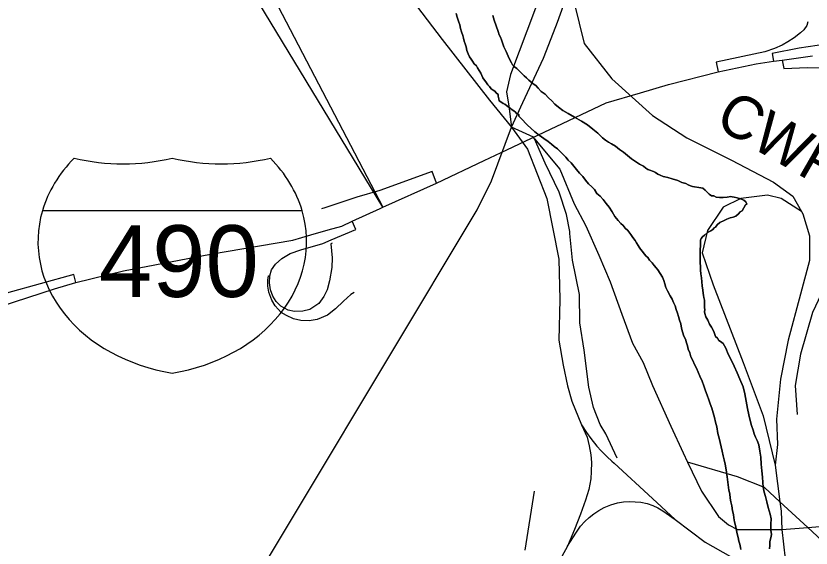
# Model space of a CAD drawing. Extents: x 0 to 96.2, y -27.5 to 31.3.
# Drawn here: x 46.371 to 47.422, y 16.88 to 17.583 of the extents above; entities that cross this region are included whole.
import ezdxf

# ---------------------------------------------------------------- set-up
doc = ezdxf.new("R2010")
doc.units = 0
for name, color, linetype in [('TB1', 7, 'Continuous'), ('TB_INDEX', 7, 'Continuous'), ('TB_PP_50x10_GRID', 7, 'Continuous'), ('TB_PROF_20x5', 7, 'Continuous'), ('TB_PROF_20x5_GRID', 7, 'Continuous'), ('TB_PSNSUM', 7, 'Continuous'), ('TB_SIGN_XS_GRID', 7, 'Continuous'), ('TB_SUPER_50x1', 7, 'Continuous')]:
    doc.layers.add(name, color=color, linetype=linetype)

msp = doc.modelspace()

# ---------------------------------------------------------------- linework, layer by layer
at = {"layer": 'TB1'}
msp.add_lwpolyline([(46.8522, 17.3284), (46.8555, 17.3299), (46.9267, 17.3616), (46.9897, 17.3916), (47.0195, 17.4057), (47.1509, 17.4678), (47.196, 17.481), (47.2332, 17.4919), (47.2987, 17.5086), (47.3491, 17.5196), (47.3717, 17.5227), (47.3835, 17.5244), (47.4236, 17.5299)], dxfattribs=at)
at = {"layer": 'TB_INDEX'}
for points in [[(46.9524, 17.5858), (46.954, 17.5809), (46.9552, 17.5771), (46.956, 17.5745), (46.9572, 17.5707), (46.9584, 17.5661), (46.9596, 17.5616), (46.9612, 17.5567), (46.9623, 17.5532), (46.9631, 17.5495)], [(46.9631, 17.5495), (46.9623, 17.5532), (46.9612, 17.5567), (46.9596, 17.5616), (46.9584, 17.5661), (46.9572, 17.5707), (46.956, 17.5745), (46.9552, 17.5771), (46.954, 17.5809), (46.9524, 17.5858)], [(47.2058, 17.3799), (47.2031, 17.3817), (47.2001, 17.3843), (47.1947, 17.3869), (47.1897, 17.3903), (47.1844, 17.394), (47.179, 17.3982), (47.1736, 17.4026), (47.1682, 17.4064), (47.1629, 17.4105), (47.1579, 17.4135), (47.1537, 17.4161), (47.1498, 17.4187), (47.146, 17.4217), (47.1395, 17.4277), (47.1333, 17.4329), (47.126, 17.4386), (47.118, 17.4438), (47.1088, 17.449), (47.1004, 17.4538), (47.0935, 17.4579), (47.0877, 17.462), (47.0828, 17.4662), (47.0789, 17.4703), (47.0747, 17.4744), (47.07, 17.4793), (47.0647, 17.483), (47.0608, 17.4872), (47.0577, 17.4906), (47.0543, 17.4928), (47.0512, 17.4954), (47.0485, 17.498), (47.0454, 17.5007), (47.0424, 17.5037), (47.0393, 17.5067), (47.0358, 17.5101), (47.0327, 17.5131), (47.0297, 17.5153), (47.027, 17.5179), (47.0258, 17.5206), (47.0235, 17.5247), (47.0211, 17.5296), (47.0184, 17.5357), (47.0157, 17.5417), (47.0137, 17.547), (47.0125, 17.5512), (47.0109, 17.5546), (47.0094, 17.5576), (47.0082, 17.5622), (47.0026, 17.5769), (47.001, 17.5834)], [(47.001, 17.5834), (47.0026, 17.5769), (47.0082, 17.5622), (47.0094, 17.5576), (47.0109, 17.5546), (47.0125, 17.5512), (47.0137, 17.547), (47.0157, 17.5417), (47.0184, 17.5357), (47.0211, 17.5296), (47.0235, 17.5247), (47.0258, 17.5206), (47.027, 17.5179), (47.0297, 17.5153), (47.0327, 17.5131), (47.0358, 17.5101), (47.0393, 17.5067), (47.0424, 17.5037), (47.0454, 17.5007), (47.0485, 17.498), (47.0512, 17.4954), (47.0543, 17.4928), (47.0577, 17.4906), (47.0608, 17.4872), (47.0647, 17.483), (47.07, 17.4793), (47.0747, 17.4744), (47.0789, 17.4703), (47.0828, 17.4662), (47.0877, 17.462), (47.0935, 17.4579), (47.1004, 17.4538), (47.1088, 17.449), (47.118, 17.4438), (47.126, 17.4386), (47.1333, 17.4329), (47.1395, 17.4277), (47.146, 17.4217), (47.1498, 17.4187), (47.1537, 17.4161), (47.1579, 17.4135), (47.1629, 17.4105), (47.1682, 17.4064), (47.1736, 17.4026), (47.179, 17.3982), (47.1844, 17.394), (47.1897, 17.3903), (47.1947, 17.3869), (47.2001, 17.3843), (47.2031, 17.3817), (47.2058, 17.3799)], [(46.9631, 17.5495), (46.9643, 17.5457), (46.9655, 17.5419), (46.9664, 17.537), (46.9683, 17.5328), (46.9703, 17.5286), (46.9722, 17.5256), (46.9741, 17.523), (46.9765, 17.5192), (46.9792, 17.5166), (46.9807, 17.5139), (46.983, 17.5106), (46.985, 17.5072), (46.9862, 17.5041), (46.9877, 17.5011), (46.9901, 17.4977), (46.9916, 17.4955), (46.9943, 17.4917), (46.9966, 17.4894), (46.9989, 17.4864), (47.0016, 17.4846), (47.0035, 17.4831), (47.0055, 17.4812), (47.0078, 17.4789), (47.0078, 17.4767), (47.009, 17.4732), (47.0094, 17.4706), (47.0129, 17.4684), (47.0148, 17.4672), (47.0167, 17.4661), (47.019, 17.4642), (47.0224, 17.4616), (47.0244, 17.4605), (47.0263, 17.4586), (47.0286, 17.4571), (47.0309, 17.4556), (47.0324, 17.4538), (47.0351, 17.4523), (47.0355, 17.4504), (47.0378, 17.4474), (47.0467, 17.4384), (47.0513, 17.4342), (47.0563, 17.4297), (47.062, 17.4252), (47.0682, 17.4208), (47.0739, 17.4166), (47.0785, 17.4133), (47.082, 17.4103), (47.0862, 17.4069), (47.0905, 17.4032), (47.0939, 17.3998), (47.0974, 17.396), (47.1005, 17.3923), (47.1043, 17.3885), (47.1078, 17.3844), (47.1113, 17.3799), (47.1155, 17.375), (47.1198, 17.3705), (47.1236, 17.3656), (47.1275, 17.3607), (47.1317, 17.3569), (47.1352, 17.3532), (47.1383, 17.3479), (47.1429, 17.3445), (47.1468, 17.34), (47.1506, 17.3347), (47.1549, 17.3298), (47.1587, 17.3238), (47.1622, 17.3178), (47.1665, 17.3125), (47.17, 17.3084), (47.173, 17.3057), (47.1757, 17.3023), (47.1792, 17.299), (47.1831, 17.2941), (47.1858, 17.2899), (47.1889, 17.2858), (47.1908, 17.2828), (47.1928, 17.2794), (47.1943, 17.2771), (47.1962, 17.2745), (47.1986, 17.2715), (47.2009, 17.2685), (47.2036, 17.2654), (47.2059, 17.2636), (47.2082, 17.2598), (47.2113, 17.2564), (47.214, 17.253), (47.2167, 17.25), (47.219, 17.247), (47.2252, 17.2376), (47.2268, 17.233), (47.2284, 17.2285), (47.2296, 17.224), (47.2316, 17.2194), (47.2354, 17.213), (47.2378, 17.2085), (47.2397, 17.2039), (47.2417, 17.1998), (47.2433, 17.1949), (47.2449, 17.1899)], [(47.2449, 17.1899), (47.2433, 17.1949), (47.2417, 17.1998), (47.2397, 17.2039), (47.2378, 17.2085), (47.2354, 17.213), (47.2316, 17.2194), (47.2296, 17.224), (47.2284, 17.2285), (47.2268, 17.233), (47.2252, 17.2376), (47.219, 17.247), (47.2167, 17.25), (47.214, 17.253), (47.2113, 17.2564), (47.2082, 17.2598), (47.2059, 17.2636), (47.2036, 17.2654), (47.2009, 17.2685), (47.1986, 17.2715), (47.1962, 17.2745), (47.1943, 17.2771), (47.1928, 17.2794), (47.1908, 17.2828), (47.1889, 17.2858), (47.1858, 17.2899), (47.1831, 17.2941), (47.1792, 17.299), (47.1757, 17.3023), (47.173, 17.3057), (47.17, 17.3084), (47.1665, 17.3125), (47.1622, 17.3178), (47.1587, 17.3238), (47.1549, 17.3298), (47.1506, 17.3347), (47.1468, 17.34), (47.1429, 17.3445), (47.1383, 17.3479), (47.1352, 17.3532), (47.1317, 17.3569), (47.1275, 17.3607), (47.1236, 17.3656), (47.1198, 17.3705), (47.1155, 17.375), (47.1113, 17.3799), (47.1078, 17.3844), (47.1043, 17.3885), (47.1005, 17.3923), (47.0974, 17.396), (47.0939, 17.3998), (47.0905, 17.4032), (47.0862, 17.4069), (47.082, 17.4103), (47.0785, 17.4133), (47.0739, 17.4166), (47.0682, 17.4208), (47.062, 17.4252), (47.0563, 17.4297), (47.0513, 17.4342), (47.0467, 17.4384), (47.0378, 17.4474), (47.0355, 17.4504), (47.0351, 17.4523), (47.0324, 17.4538), (47.0309, 17.4556), (47.0286, 17.4571), (47.0263, 17.4586), (47.0244, 17.4605), (47.0224, 17.4616), (47.019, 17.4642), (47.0167, 17.4661), (47.0148, 17.4672), (47.0129, 17.4684), (47.0094, 17.4706), (47.009, 17.4732), (47.0078, 17.4767), (47.0078, 17.4789), (47.0055, 17.4812), (47.0035, 17.4831), (47.0016, 17.4846), (46.9989, 17.4864), (46.9966, 17.4894), (46.9943, 17.4917), (46.9916, 17.4955), (46.9901, 17.4977), (46.9877, 17.5011), (46.9862, 17.5041), (46.985, 17.5072), (46.983, 17.5106), (46.9807, 17.5139), (46.9792, 17.5166), (46.9765, 17.5192), (46.9741, 17.523), (46.9722, 17.5256), (46.9703, 17.5286), (46.9683, 17.5328), (46.9664, 17.537), (46.9655, 17.5419), (46.9643, 17.5457), (46.9631, 17.5495)], [(47.3357, 17.0736), (47.334, 17.0835), (47.3316, 17.0926), (47.3273, 17.1028), (47.3238, 17.1111), (47.3199, 17.1198), (47.316, 17.1285), (47.3121, 17.136), (47.3089, 17.1436), (47.3054, 17.15), (47.3016, 17.1526), (47.2997, 17.1537), (47.2977, 17.1568), (47.2954, 17.159), (47.2942, 17.1617), (47.2934, 17.1643), (47.2923, 17.1677), (47.2899, 17.1715), (47.2872, 17.1756), (47.2849, 17.1805), (47.2825, 17.1851), (47.2813, 17.1896), (47.2805, 17.1919), (47.2809, 17.1946), (47.2808, 17.1968), (47.2808, 17.2003), (47.2808, 17.2037), (47.2807, 17.2071), (47.2799, 17.2105), (47.2795, 17.2132), (47.2791, 17.2162), (47.2786, 17.2204), (47.2778, 17.2261), (47.277, 17.2314), (47.2765, 17.2367), (47.2757, 17.242), (47.2752, 17.2469), (47.2752, 17.2515), (47.2751, 17.2564), (47.275, 17.2614), (47.2749, 17.2671), (47.2749, 17.2731), (47.2752, 17.2796), (47.2754, 17.2865), (47.2762, 17.2887), (47.278, 17.291), (47.2807, 17.293), (47.2848, 17.2964), (47.2889, 17.2988), (47.2916, 17.3007), (47.2934, 17.3026), (47.2953, 17.3038), (47.2972, 17.3065), (47.3009, 17.3096), (47.3028, 17.3107), (47.3051, 17.3115), (47.3074, 17.3127), (47.3104, 17.3142), (47.3145, 17.3158), (47.3187, 17.317), (47.3221, 17.3182), (47.3255, 17.3213), (47.3277, 17.3239), (47.3303, 17.3251), (47.3326, 17.3293), (47.3348, 17.3331), (47.3367, 17.3339), (47.3355, 17.337), (47.3328, 17.3392), (47.3282, 17.3411), (47.3237, 17.3425), (47.3198, 17.3432), (47.3172, 17.3436), (47.3153, 17.3439), (47.3107, 17.3431), (47.3054, 17.3427), (47.3005, 17.343), (47.2963, 17.3433), (47.2932, 17.3448), (47.2898, 17.3451), (47.2868, 17.3474), (47.2841, 17.35), (47.2814, 17.3526), (47.2783, 17.3549), (47.276, 17.3556), (47.265, 17.3574), (47.2623, 17.3581), (47.2592, 17.3596), (47.2558, 17.3611), (47.2509, 17.3625), (47.2455, 17.3651), (47.2379, 17.3673), (47.2322, 17.3692), (47.2284, 17.3699), (47.2261, 17.3706), (47.2222, 17.3725), (47.2192, 17.3736), (47.2157, 17.3758), (47.2131, 17.3773), (47.2085, 17.3791), (47.2058, 17.3799)], [(47.2058, 17.3799), (47.2085, 17.3791), (47.2131, 17.3773), (47.2157, 17.3758), (47.2192, 17.3736), (47.2222, 17.3725), (47.2261, 17.3706), (47.2284, 17.3699), (47.2322, 17.3692), (47.2379, 17.3673), (47.2455, 17.3651), (47.2509, 17.3625), (47.2558, 17.3611), (47.2592, 17.3596), (47.2623, 17.3581), (47.265, 17.3574), (47.276, 17.3556), (47.2783, 17.3549), (47.2814, 17.3526), (47.2841, 17.35), (47.2868, 17.3474), (47.2898, 17.3451), (47.2932, 17.3448), (47.2963, 17.3433), (47.3005, 17.343), (47.3054, 17.3427), (47.3107, 17.3431), (47.3153, 17.3439), (47.3172, 17.3436), (47.3198, 17.3432), (47.3237, 17.3425), (47.3282, 17.3411), (47.3328, 17.3392), (47.3355, 17.337), (47.3367, 17.3339), (47.3348, 17.3331), (47.3326, 17.3293), (47.3303, 17.3251), (47.3277, 17.3239), (47.3255, 17.3213), (47.3221, 17.3182), (47.3187, 17.317), (47.3145, 17.3158), (47.3104, 17.3142), (47.3074, 17.3127), (47.3051, 17.3115), (47.3028, 17.3107), (47.3009, 17.3096), (47.2972, 17.3065), (47.2953, 17.3038), (47.2934, 17.3026), (47.2916, 17.3007), (47.2889, 17.2988), (47.2848, 17.2964), (47.2807, 17.293), (47.278, 17.291), (47.2762, 17.2887), (47.2754, 17.2865), (47.2752, 17.2796), (47.2749, 17.2731), (47.2749, 17.2671), (47.275, 17.2614), (47.2751, 17.2564), (47.2752, 17.2515), (47.2752, 17.2469), (47.2757, 17.242), (47.2765, 17.2367), (47.277, 17.2314), (47.2778, 17.2261), (47.2786, 17.2204), (47.2791, 17.2162), (47.2795, 17.2132), (47.2799, 17.2105), (47.2807, 17.2071), (47.2808, 17.2037), (47.2808, 17.2003), (47.2808, 17.1968), (47.2809, 17.1946), (47.2805, 17.1919), (47.2813, 17.1896), (47.2825, 17.1851), (47.2849, 17.1805), (47.2872, 17.1756), (47.2899, 17.1715), (47.2923, 17.1677), (47.2934, 17.1643), (47.2942, 17.1617), (47.2954, 17.159), (47.2977, 17.1568), (47.2997, 17.1537), (47.3016, 17.1526), (47.3054, 17.15), (47.3089, 17.1436), (47.3121, 17.136), (47.316, 17.1285), (47.3199, 17.1198), (47.3238, 17.1111), (47.3273, 17.1028), (47.3316, 17.0926), (47.334, 17.0835), (47.3357, 17.0736)], [(47.2449, 17.1899), (47.2464, 17.1854), (47.2477, 17.1805), (47.2492, 17.1759), (47.2501, 17.1702), (47.2517, 17.1653), (47.2533, 17.1596), (47.2556, 17.1555), (47.2568, 17.1509), (47.258, 17.1468), (47.2592, 17.1426), (47.2612, 17.1377), (47.2627, 17.1324), (47.2651, 17.1275), (47.2674, 17.1222), (47.2702, 17.1173), (47.2721, 17.112), (47.2745, 17.1067), (47.2776, 17.0999), (47.2796, 17.0938), (47.282, 17.0874), (47.2843, 17.0814), (47.2863, 17.0753), (47.2883, 17.07), (47.2903, 17.0643), (47.2922, 17.0583), (47.2938, 17.0522), (47.2954, 17.0458), (47.297, 17.0397), (47.2983, 17.031), (47.2999, 17.0249), (47.3015, 17.0192), (47.3027, 17.0135), (47.3039, 17.0075), (47.3055, 17.0014), (47.3068, 16.9961), (47.308, 16.9904), (47.3088, 16.9855), (47.3096, 16.9798), (47.3105, 16.9737), (47.313, 16.9563), (47.3142, 16.9514), (47.3147, 16.9457), (47.3155, 16.9407), (47.3167, 16.9354), (47.3175, 16.929), (47.3188, 16.9241), (47.3196, 16.9195), (47.3204, 16.9142), (47.3216, 16.9093), (47.3228, 16.9028), (47.324, 16.8983), (47.3252, 16.8934), (47.3261, 16.8888), (47.3273, 16.8846), (47.3281, 16.8805), (47.3285, 16.8778)], [(47.3285, 16.8778), (47.3281, 16.8805), (47.3273, 16.8846), (47.3261, 16.8888), (47.3252, 16.8934), (47.324, 16.8983), (47.3228, 16.9028), (47.3216, 16.9093), (47.3204, 16.9142), (47.3196, 16.9195), (47.3188, 16.9241), (47.3175, 16.929), (47.3167, 16.9354), (47.3155, 16.9407), (47.3147, 16.9457), (47.3142, 16.9514), (47.313, 16.9563), (47.3105, 16.9737), (47.3096, 16.9798), (47.3088, 16.9855), (47.308, 16.9904), (47.3068, 16.9961), (47.3055, 17.0014), (47.3039, 17.0075), (47.3027, 17.0135), (47.3015, 17.0192), (47.2999, 17.0249), (47.2983, 17.031), (47.297, 17.0397), (47.2954, 17.0458), (47.2938, 17.0522), (47.2922, 17.0583), (47.2903, 17.0643), (47.2883, 17.07), (47.2863, 17.0753), (47.2843, 17.0814), (47.282, 17.0874), (47.2796, 17.0938), (47.2776, 17.0999), (47.2745, 17.1067), (47.2721, 17.112), (47.2702, 17.1173), (47.2674, 17.1222), (47.2651, 17.1275), (47.2627, 17.1324), (47.2612, 17.1377), (47.2592, 17.1426), (47.258, 17.1468), (47.2568, 17.1509), (47.2556, 17.1555), (47.2533, 17.1596), (47.2517, 17.1653), (47.2501, 17.1702), (47.2492, 17.1759), (47.2477, 17.1805), (47.2464, 17.1854), (47.2449, 17.1899)], [(47.3665, 16.8787), (47.3668, 16.8832), (47.3671, 16.8882), (47.3685, 16.8931), (47.3692, 16.8977), (47.3684, 16.9034), (47.3683, 16.911), (47.3686, 16.9182), (47.3674, 16.9243), (47.365, 16.933), (47.363, 16.9406), (47.3613, 16.9478), (47.3597, 16.9534), (47.3581, 16.9599), (47.3577, 16.9663), (47.3572, 16.9732), (47.3563, 16.9815), (47.3554, 16.9906), (47.3549, 16.9997), (47.3537, 17.0077), (47.3524, 17.0161), (47.3501, 17.0217), (47.3481, 17.0263), (47.3465, 17.0304), (47.3449, 17.0353), (47.343, 17.0414), (47.341, 17.0482), (47.3394, 17.0558), (47.3377, 17.0641), (47.3357, 17.0736)], [(47.3357, 17.0736), (47.3377, 17.0641), (47.3394, 17.0558), (47.341, 17.0482), (47.343, 17.0414), (47.3449, 17.0353), (47.3465, 17.0304), (47.3481, 17.0263), (47.3501, 17.0217), (47.3524, 17.0161), (47.3537, 17.0077), (47.3549, 16.9997), (47.3554, 16.9906), (47.3563, 16.9815), (47.3572, 16.9732), (47.3577, 16.9663), (47.3581, 16.9599), (47.3597, 16.9534), (47.3613, 16.9478), (47.363, 16.9406), (47.365, 16.933), (47.3674, 16.9243), (47.3686, 16.9182), (47.3683, 16.911), (47.3684, 16.9034), (47.3692, 16.8977), (47.3685, 16.8931), (47.3671, 16.8882), (47.3668, 16.8832), (47.3665, 16.8787)]]:
    msp.add_lwpolyline(points, dxfattribs=at)
at = {"layer": 'TB_PP_50x10_GRID'}
for points in [[(46.6615, 17.938), (46.6763, 17.935), (46.6986, 17.9287), (46.7213, 17.9227), (46.7264, 17.9208), (46.7328, 17.9175), (46.7381, 17.9142), (46.7445, 17.9079), (46.7495, 17.9012), (46.7547, 17.8925), (46.7726, 17.8533), (46.8033, 17.7654), (46.8228, 17.7271), (46.8391, 17.6933), (46.8523, 17.6675), (46.8874, 17.613), (46.9338, 17.5515), (46.9965, 17.4712), (47.0256, 17.4359)], [(47.0932, 17.7583), (47.0991, 17.7112), (47.0905, 17.6809), (47.0245, 17.5055), (47.0191, 17.4823), (47.0222, 17.4636), (47.0256, 17.4359)], [(47.0256, 17.4359), (47.0408, 17.4683), (47.0681, 17.527), (47.0843, 17.5686), (47.0863, 17.5746), (47.1005, 17.6141), (47.1076, 17.6455)], [(47.1076, 17.6455), (47.1086, 17.6), (47.1218, 17.5463), (47.1582, 17.4997), (47.2119, 17.451), (47.2575, 17.4217), (47.3162, 17.3923), (47.3719, 17.3629), (47.3972, 17.3447), (47.4089, 17.3241)], [(46.63, 16.7424), (46.9804, 17.3265), (46.9992, 17.3649), (47.0256, 17.4359)], [(47.0256, 17.4359), (47.0468, 17.4065), (47.0722, 17.3416), (47.088, 17.2613), (47.0897, 17.2079), (47.088, 17.1545), (47.0939, 17.1213), (47.0998, 17.094), (47.1052, 17.0738), (47.1181, 17.0423)], [(47.0561, 17.4201), (47.0549, 17.4227), (47.0256, 17.4359)], [(47.1027, 17.2952), (47.1025, 17.2978), (47.0985, 17.3204), (47.0884, 17.3497), (47.0701, 17.3882), (47.0561, 17.4201)], [(47.0561, 17.4201), (47.0894, 17.3801), (47.1086, 17.3345), (47.1238, 17.3052), (47.141, 17.2667), (47.1562, 17.2312), (47.1714, 17.1887), (47.1856, 17.1502), (47.1998, 17.1249), (47.2119, 17.0945)], [(47.4089, 17.3241), (47.382, 17.3416), (47.3639, 17.346), (47.3288, 17.3416), (47.3053, 17.3299), (47.2848, 17.2991), (47.2775, 17.2698), (47.2921, 17.2273), (47.3316, 17.1247), (47.358, 17.0543), (47.3739, 16.9891)], [(47.4089, 17.3241), (47.4104, 17.3214), (47.4195, 17.292), (47.4195, 17.2596), (47.4074, 17.215), (47.3911, 17.1542), (47.381, 17.1026), (47.376, 17.0499), (47.377, 17.0165), (47.3739, 16.9891)], [(47.1654, 16.9983), (47.1501, 17.0307), (47.143, 17.0428), (47.1342, 17.0652), (47.1279, 17.0924), (47.1218, 17.1411), (47.1159, 17.1774), (47.1156, 17.2146), (47.1063, 17.2602), (47.1027, 17.2952)], [(47.4172, 16.9068), (47.4862, 16.9124), (47.576, 16.9315), (47.6098, 16.9475), (47.64, 16.9661), (47.6686, 16.9932), (47.6869, 17.0165), (47.7, 17.0408), (47.7062, 17.0612), (47.7099, 17.0925), (47.7105, 17.1744), (47.701, 17.2018), (47.6879, 17.2211), (47.6555, 17.2565), (47.6251, 17.2809), (47.5856, 17.289), (47.5481, 17.2819), (47.5157, 17.2667), (47.4691, 17.2414), (47.4347, 17.215), (47.4236, 17.1907), (47.4074, 17.136), (47.4003, 17.0945), (47.4033, 17.056)], [(47.2119, 17.0945), (47.2362, 17.0408), (47.2524, 17.0053), (47.2583, 16.9931)], [(47.1181, 17.0423), (47.1254, 17.026), (47.1283, 17.0147), (47.1306, 17.0029), (47.1313, 16.9928), (47.1311, 16.9809), (47.1304, 16.9711), (47.1277, 16.9569), (47.1234, 16.9427), (47.1166, 16.9242), (47.1089, 16.9043), (47.0997, 16.8823)], [(47.1181, 17.0423), (47.1247, 17.0324), (47.1306, 17.0243), (47.1383, 17.0143), (47.1441, 17.008), (47.1522, 17.0003), (47.1584, 16.9944), (47.1611, 16.9919)], [(47.3804, 16.9407), (47.3598, 16.9597), (47.3243, 16.9739), (47.2615, 16.9922), (47.2583, 16.9931)], [(47.2583, 16.9931), (47.2767, 16.9547), (47.299, 16.9212), (47.3122, 16.9101), (47.3243, 16.904), (47.3517, 16.904), (47.383, 16.904)], [(47.1611, 16.9919), (47.212, 16.945), (47.2421, 16.9172)], [(47.3739, 16.9891), (47.3804, 16.9407)], [(47.0435, 16.8768), (47.0561, 16.9547)], [(47.0997, 16.8823), (47.1105, 16.8994), (47.1168, 16.9085), (47.1227, 16.9148), (47.1284, 16.9201), (47.1344, 16.9248), (47.141, 16.9293), (47.1481, 16.9331), (47.1568, 16.9367), (47.1658, 16.9395), (47.1737, 16.9405), (47.181, 16.9411), (47.1892, 16.9409), (47.1967, 16.9401), (47.2048, 16.9385), (47.2126, 16.9358), (47.2188, 16.9328), (47.2256, 16.929), (47.2421, 16.9172)], [(47.3804, 16.9407), (47.382, 16.9283), (47.383, 16.904)], [(47.4172, 16.9068), (47.3804, 16.9407)], [(47.2421, 16.9172), (47.2817, 16.8875), (47.3149, 16.8683), (47.3758, 16.8254)], [(47.383, 16.904), (47.3871, 16.8655), (47.3758, 16.8254)], [(47.383, 16.904), (47.4172, 16.9068)], [(47.6826, 16.6275), (47.6602, 16.6629), (47.5995, 16.7294), (47.5726, 16.7615), (47.5467, 16.7916), (47.516, 16.8183), (47.4676, 16.8603), (47.4172, 16.9068)], [(47.0997, 16.8823), (47.0342, 16.7626)]]:
    msp.add_lwpolyline(points, dxfattribs=at)
at = {"layer": 'TB_PROF_20x5_GRID'}
for points in [[(47.4173, 17.5747), (47.4157, 17.5699), (47.4118, 17.5643), (47.4076, 17.5604), (47.3991, 17.5537), (47.3909, 17.5485), (47.3833, 17.5441), (47.3731, 17.5395), (47.3605, 17.5354), (47.296, 17.5216), (47.2987, 17.5086)], [(47.4414, 17.5453), (47.4059, 17.54), (47.3701, 17.5332), (47.3717, 17.5227)], [(47.3835, 17.5244), (47.3853, 17.5132), (47.4167, 17.5145), (47.4396, 17.5141), (47.4607, 17.5132), (47.481, 17.5096), (47.5028, 17.5026), (47.5627, 17.4844), (47.5692, 17.4821), (47.5819, 17.4775), (47.5956, 17.4723), (47.6033, 17.469), (47.6086, 17.4653), (47.6118, 17.4685)], [(46.9267, 17.3616), (46.9206, 17.3771), (46.8518, 17.3522), (46.8213, 17.3433), (46.779, 17.3293), (46.7745, 17.3278)], [(46.7887, 17.2823), (46.787, 17.2817), (46.7886, 17.2629), (46.7883, 17.2505), (46.785, 17.2325), (46.7819, 17.2207), (46.7778, 17.2119), (46.7708, 17.2026), (46.7592, 17.1947), (46.7497, 17.1926), (46.7389, 17.1923), (46.7304, 17.1939), (46.7209, 17.199), (46.7147, 17.2055), (46.7101, 17.2124), (46.707, 17.2207), (46.7059, 17.2302), (46.7062, 17.2392), (46.7085, 17.2472), (46.7139, 17.2549), (46.7222, 17.2621), (46.733, 17.2686), (46.7474, 17.2735), (46.7762, 17.2822), (46.7873, 17.2868), (46.82, 17.3005), (46.8151, 17.3114)], [(46.45, 17.2306), (46.4471, 17.241), (46.3581, 17.2162), (46.2873, 17.1957), (46.2463, 17.1877), (46.2141, 17.1826), (46.1876, 17.1774), (46.1837, 17.1762), (46.1613, 17.1694), (46.1368, 17.1594), (46.1155, 17.1462), (46.1013, 17.1342), (46.0995, 17.1319), (46.0949, 17.1258), (46.094, 17.1246), (46.0847, 17.1125), (46.0734, 17.0935), (46.0666, 17.0749), (46.0637, 17.0577), (46.0615, 17.0373), (46.0613, 17.0147), (46.0634, 16.9969), (46.0675, 16.9579), (46.0651, 16.9573)], [(46.8179, 17.2173), (46.8133, 17.2148), (46.8035, 17.2057), (46.7929, 17.1957), (46.7824, 17.1875), (46.7688, 17.1818), (46.7582, 17.18), (46.7471, 17.1802), (46.7376, 17.1826), (46.7283, 17.1867), (46.7211, 17.1908), (46.7132, 17.1998), (46.7088, 17.207), (46.7049, 17.2176), (46.7037, 17.2255), (46.7037, 17.2335), (46.7047, 17.2394), (46.7062, 17.2392)]]:
    msp.add_lwpolyline(points, dxfattribs=at)
at = {"layer": 'TB_PSNSUM'}
for points in [[(46.7605, 17.2934), (46.7832, 17.2999), (46.8012, 17.3051), (46.8151, 17.3114), (46.8522, 17.3284)], [(46.1791, 17.1461), (46.184, 17.1471), (46.1944, 17.1493), (46.2287, 17.1581), (46.3514, 17.1992), (46.4217, 17.2219), (46.45, 17.2306), (46.5128, 17.2458), (46.6277, 17.2678), (46.7368, 17.2865), (46.7605, 17.2934)]]:
    msp.add_lwpolyline(points, dxfattribs=at)
at = {"layer": 'TB_SIGN_XS_GRID'}
msp.add_line((46.7489, 17.3253), (46.4056, 17.3253), dxfattribs=at)
msp.add_line((46.7489, 17.3253), (46.4056, 17.3253), dxfattribs=at)
for centre, start_param, end_param in [((46.6217, 17.2847), 2.47259, 2.911027), ((46.5124, 17.5647), 4.415841, 5.008937), ((46.6421, 17.5647), 4.415841, 5.008937), ((46.5329, 17.2847), 0.230566, 0.669003), ((46.6217, 17.2847), 2.911027, 4.511031), ((46.5329, 17.2847), 4.913747, 6.513751)]:
    msp.add_ellipse(centre, major_axis=(0.2219, 0), ratio=0.8, start_param=start_param, end_param=end_param, dxfattribs=at)
at = {"layer": 'TB_SUPER_50x1'}
msp.add_lwpolyline([(45.6693, 19.6035), (46.8555, 17.3299), (45.4754, 19.6035)], close=True, dxfattribs=at)

# ---------------------------------------------------------------- texts
at = {"layer": 'TB_PROF_20x5'}
msp.add_text('CWRO', height=0.05663, rotation=330.0565, dxfattribs=at).set_placement((47.292, 17.438))
at = {"layer": 'TB_SIGN_XS_GRID'}
msp.add_text('490', height=0.0947, dxfattribs=at).set_placement((46.4804, 17.2114))

doc.saveas('drawing.dxf')
